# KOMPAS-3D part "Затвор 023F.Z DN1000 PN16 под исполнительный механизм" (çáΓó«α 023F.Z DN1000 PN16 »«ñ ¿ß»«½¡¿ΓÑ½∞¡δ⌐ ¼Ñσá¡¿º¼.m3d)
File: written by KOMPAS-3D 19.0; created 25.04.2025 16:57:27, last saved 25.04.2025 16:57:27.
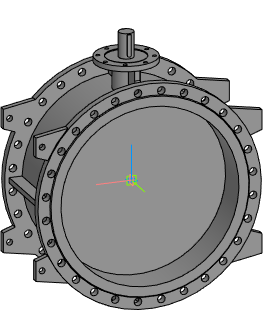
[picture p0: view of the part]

Document properties: Автор: Евгений; Полное имя файла: E:\Dendor Работа Сачек\3D для проекитирвщиков\1.7 Тип 023F.Z Затвор дисковый поворотный фланцевый с двумя эксцентриками\stp_Тип 023F.Z. Затвор под исполн. механизм\Затвор 023F.Z DN1000 PN16 под исполнительный механизм.m3d

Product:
- Part/product: Затвор 023F.Z DN1000 PN16 под исполнительный механизм

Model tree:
1. Операция без истории:1  (labels: Затвор 023F.Z DN1000 PN16 под исполнительный механизм)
